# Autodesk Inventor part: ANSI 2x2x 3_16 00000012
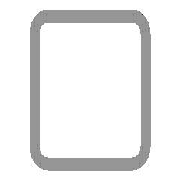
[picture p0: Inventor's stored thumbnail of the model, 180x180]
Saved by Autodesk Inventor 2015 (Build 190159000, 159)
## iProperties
IsCustomPart: 1
Created: 2007-02
Part Number: ANSI 2x2x 3_16 00000012
Material: Steel
Document SubType Name: Modeling
Standard: AISC
Designer: Autodesk, Inc.
Size Designation: 2x2x3/16
Stock Number: 2x2x 3/16
Density: 7.85 g/cm^3
Description: Tube
Standards Organization: ANSI
Language: en-US
Categories: <MemberInstance><Categories><Category DisplayName="Structural Shapes" InternalName="089c4875-fa83-4c05-b084-43b9cc11f5ed" Mnemonic="GRDR"><CategoryParameter Dis
Mass: 4523.85 g
Surface Area: 2436.47 cm^2
Volume: 576.287 cm^3
Appearance: Steel
_FrameMemberDoc: Frame Member File
_Version: 15.0.0
_CCFamilyMember: 1
_CCFamilyDisplayName: ANSI AISC (Square) - Tube
G_L: 27.716 in
G_W: 2.000 in
G_H: 2.000 in
+9C539298-48EE-4858-83B2-F8D672A3B8EA+CUTDETAIL1: Cut
Author: Autodesk, Inc.
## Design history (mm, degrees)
node "Start plane"
node "End plane"
sketch "Sketch"
  geometry: L1 (-25.4, -15.875)-(-25.4, 15.875); L2 (-15.875, 25.4)-(15.875, 25.4); L3 (25.4, 15.875)-(25.4, -15.875); L4 (15.875, -25.4)-(-15.875, -25.4); L5 (-15.875, 20.637)-(15.875, 20.638); L6 (20.637, 15.875)-(20.637, -15.875); L7 (15.875, -20.637)-(-15.875, -20.638); L8 (-20.637, -15.875)-(-20.637, 15.875); L9 (0, 38.322)-(0, -38.322) reference; L10 (-38.322, 0)-(38.322, 0) reference; A1 r 9.525 centre (-15.875, -15.875) between (-25.4, -15.875) and (-15.875, -25.4); A2 r 9.525 centre (-15.875, 15.875) between (-15.875, 25.4) and (-25.4, 15.875); A3 r 9.525 centre (15.875, 15.875) between (25.4, 15.875) and (15.875, 25.4); A4 r 9.525 centre (15.875, -15.875) between (15.875, -25.4) and (25.4, -15.875); A5 r 4.762 centre (-15.875, 15.875) between (-15.875, 20.637) and (-20.637, 15.875); A6 r 4.762 centre (15.875, 15.875) between (20.637, 15.875) and (15.875, 20.638); A7 r 4.762 centre (15.875, -15.875) between (15.875, -20.637) and (20.637, -15.875); A8 r 4.762 centre (-15.875, -15.875) between (-20.637, -15.875) and (-15.875, -20.638)
  constraints: 16 end point, 16 point on circle, 8 centre point, 8 tangent, 4 parallel, 3 equal radius, 2 perpendicular, 7 other
  dimensions: "d10" = 50.8 distance between parallel lines of L2 L4 (= G_H); "d11" = 50.8 distance between parallel lines of L1 L3 (= G_W); "d12" = 4.7625 distance between parallel lines of L3 L6 (= G_T); "d15" = 25.4 distance between parallel lines of L2 L10 (= 0.5 x d10); "d16" = 25.4 distance between parallel lines of L9 L3 (= 0.5 x d11); "d17" = 9.525 radius of A1 (= G_IR)
extrude "Body" new body sketch "Sketch" stored distance "d3" = 703.9864 (= G_L); taper "d4" = 0 deg
node "Driven Length"
  sketch "Sketch3"
    geometry: L1 (0, 0)-(10, 0) reference
    constraints: 2 end point, 1 horizontal
  workplane "Work Plane4"
  sketch "Sketch4"
    geometry: L1 (-2, 0)-(12, 0) reference; L2 (-2, 703.986)-(12, 703.986) reference
    dimensions: "d19" = 703.9864 distance between parallel lines of L1 L2 (derived)
workplane "Work Plane3"
split "Split1"
body "Solid1"
other parameters: "G_W" = 50.8 [user parameter; used in 1 equation term], "G_H" = 50.8 [user parameter; used in 1 equation term], "G_T" = 4.7625 [user parameter; used in 1 equation term], "G_IR" = 9.525 [user parameter; used in 1 equation term], "G_L" = 703.9864 (= d19) [user parameter; used in 1 equation term], "G_OFFSET_START" = 0 [user parameter; used in 1 equation term], "G_OFFSET_END" = -50.8 [user parameter; used in 1 equation term], "d13" = 0 (computed from G_OFFSET_START), "d14" = 703.9864 (= G_OFFSET_END + B_L), "B_L" = 754.7864 [user parameter; used in 1 equation term], "d18" = 90 deg
